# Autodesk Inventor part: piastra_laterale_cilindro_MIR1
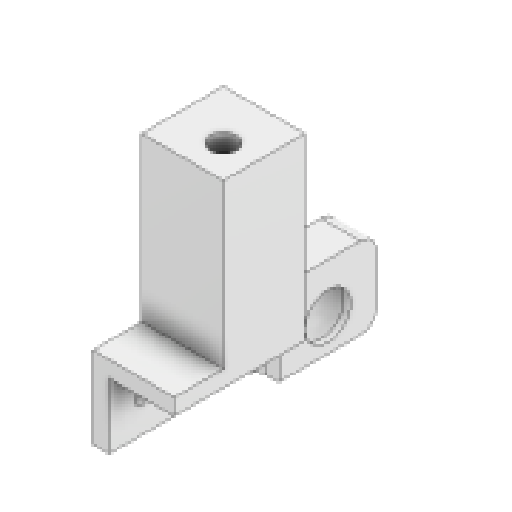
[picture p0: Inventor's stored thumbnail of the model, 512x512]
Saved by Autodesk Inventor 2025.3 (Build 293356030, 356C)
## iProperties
Created: 2025-09
Part Number: piastra_laterale_cilindro_MIR1
Material: Plastica ABS
Document SubType Name: Modeling
Designer: R5800u
Density: 1.06 g/cm^3
Appearance: Liscia - Bianco
Author: R5800u
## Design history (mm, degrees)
derived "piastra_laterale_cilindro.ipt"
  sketch "Schizzo1"
    geometry: L1 (2.5, 10)-(-2.5, 10) reference; L2 (-2.5, 10)-(-2.5, -10) reference; L3 (-2.5, -10)-(2.5, -10) reference; L4 (2.5, -10)-(2.5, 10) reference; L5 (2.5, 10)-(-2.5, -10) reference; L6 (-2.5, 10)-(2.5, -10) reference; 1 further point
  sketch "Schizzo2"
    geometry: L1 (-50, 20)-(0, 20) reference; L2 (0, 0)-(-25, 0) reference; L3 (-25, 0)-(-25, 20) reference; L4 (-25, 20)-(0, 20) reference; L5 (0, 20)-(0, 0) reference; L6 (-30, 1)-(-30, 6.7) reference; L7 (-25, 0)-(-30, 0) reference; L8 (-30, 0)-(-30, 20) reference; L9 (-30, 20)-(-25, 20) reference; L10 (-25, 20)-(-25, 0) reference; 1 further point
  sketch "Schizzo3"
    geometry: C1 r 4 at (10, 10) reference; C2 r 8 at (10, 10) reference; 1 further point
  sketch "Schizzo4"
    geometry: L1 (2.5, -10)-(-2.5, -10) reference; L2 (-2.5, -10)-(-2.5, 10) reference; L3 (-2.5, 10)-(2.5, 10) reference; L4 (2.5, 10)-(2.5, -10) reference; 1 further point
feature "Solido1::piastra_laterale_cilindro.ipt"
tag "Lavorazione contrassegno1"
node "Solido1"
